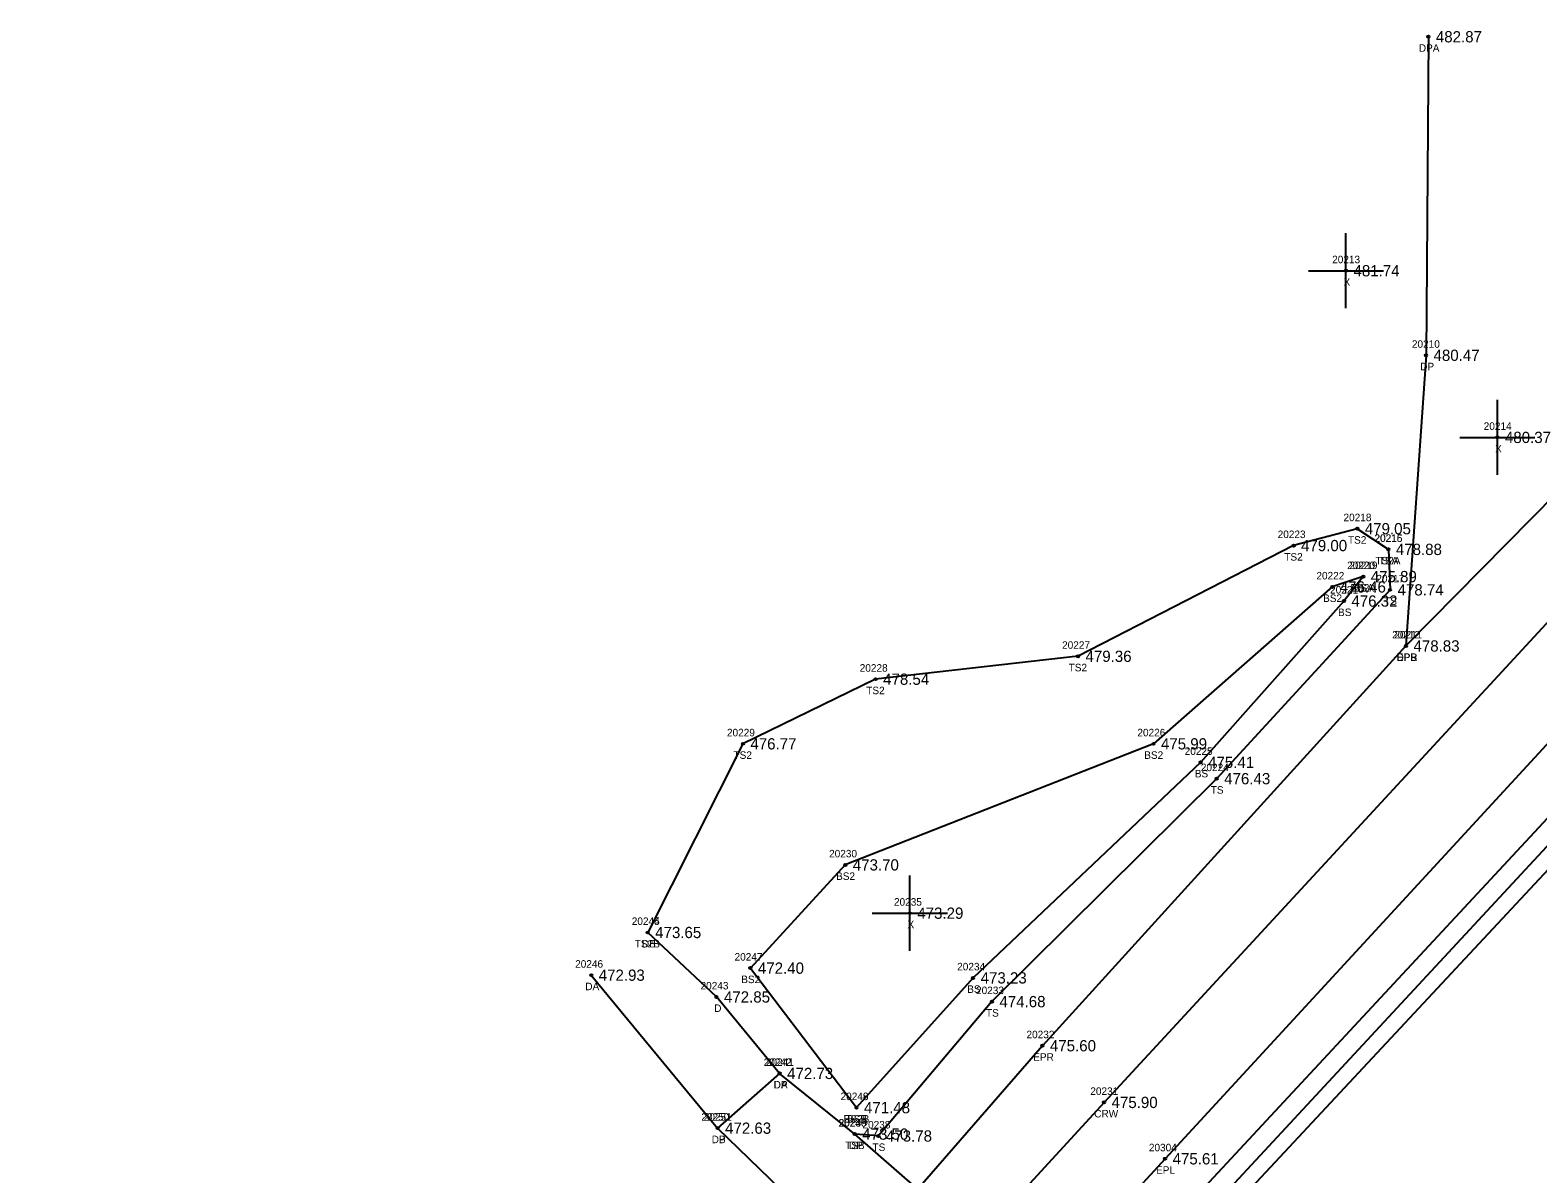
# Model space of a CAD drawing. Extents: x 1741010 to 1742139, y 749382 to 750625.
# Drawn here: x 1741600.6 to 1741801.4, y 750217 to 750369.4 of the extents above; entities that cross this region are included whole.
import ezdxf

# ---------------------------------------------------------------- set-up
doc = ezdxf.new("R2010")
doc.units = 0
for name, color, linetype in [('RD_DTM_BkLn1', 7, 'Continuous'), ('RD_DTM_BkLn2', 7, 'Continuous'), ('RD_DTM_BkLn_txCode', 7, 'Continuous'), ('RD_EX_Driveway', 7, 'Continuous'), ('RD_EX_Driveway_txCode', 7, 'Continuous'), ('RD_EX_Misc', 7, 'Continuous'), ('RD_EX_Misc_txCode', 7, 'Continuous'), ('RD_EX_Road', 7, 'Continuous'), ('RD_EX_Road_txCode', 7, 'Continuous'), ('RD_EX_TX_Driveway_ELEV', 7, 'Continuous'), ('RD_EX_TX_Misc_ELEV', 7, 'Continuous'), ('RD_EX_TX_Road_ELEV', 7, 'Continuous'), ('RD_HC_Survey_ELEV', 7, 'Continuous'), ('RD_HC_Survey_txCode', 7, 'Continuous'), ('RD_SMD_Locator', 7, 'Continuous')]:
    doc.layers.add(name, color=color, linetype=linetype)

msp = doc.modelspace()

# ---------------------------------------------------------------- linework, layer by layer
at = {"layer": 'RD_DTM_BkLn1'}
msp.add_lwpolyline([(1742095.1, 750579.47), (1742056.96, 750547.11), (1742019.74, 750514.22), (1741983.45, 750480.17), (1741948.01, 750445.01), (1741913.15, 750409.3), (1741879.03, 750372.99), (1741811.59, 750300.09), (1741743.65, 750226.52), (1741676.29, 750153.06), (1741642.32, 750115.53), (1741610.32, 750077.63)], dxfattribs=at)
at = {"layer": 'RD_DTM_BkLn2'}
for points in [[(1742105.6, 750567.48), (1742094.25, 750560.49), (1742091.64, 750555.7), (1742067.93, 750534.94), (1742031.73, 750501.95), (1741994.85, 750467.63), (1741959.82, 750432.06), (1741925.8, 750396.31), (1741891.25, 750362.62), (1741824.36, 750287.7), (1741756.44, 750214.6), (1741688.69, 750142.04), (1741655.55, 750103.43), (1741644.64, 750083.31), (1741626.06, 750060.3), (1741620, 750055.3), (1741614.97, 750059.12), (1741617.5, 750064.27), (1741619.23, 750067.96)], [(1742107.37, 750564.98), (1742099.21, 750558.66), (1742095.99, 750559.5), (1742095.15, 750554.39), (1742069.73, 750532.61), (1742034.06, 750499.81), (1741997.6, 750464.99), (1741961.88, 750429.54), (1741928.13, 750394.17), (1741895.34, 750359.02), (1741826.5, 750286.36), (1741758.73, 750213.29), (1741690.1, 750140.59), (1741658.36, 750099.77), (1741650.43, 750077.87), (1741632.9, 750061.59), (1741621.97, 750051.56), (1741618.99, 750048.78), (1741611.88, 750047.79)], [(1742108.6, 750563.87), (1742101.48, 750556.48), (1742102.57, 750548.5), (1742101.05, 750532.99), (1742105.06, 750513.92), (1742103.27, 750510.53), (1742100.54, 750509.6), (1742099.13, 750514.58), (1742095.78, 750530.6), (1742094.19, 750550.08), (1742071, 750531.59), (1742035.26, 750498.87), (1741998.91, 750463.73), (1741964.71, 750427.12), (1741930.26, 750392.09), (1741896.36, 750357.96), (1741828.15, 750284.74), (1741760.22, 750211.9), (1741691.37, 750138.81), (1741661.95, 750096.11), (1741655.14, 750072.69), (1741637.21, 750056.01), (1741627.61, 750046.43), (1741623.09, 750045.5)], [(1741781.51, 750300.19), (1741777.38, 750302.95), (1741768.89, 750300.7), (1741740.18, 750285.95), (1741713.23, 750282.9), (1741695.55, 750274.29), (1741682.87, 750249.16)], [(1741781.51, 750300.19), (1741781.74, 750294.8), (1741758.65, 750269.65), (1741728.72, 750239.95), (1741713.6, 750222.05), (1741710.44, 750222.3)], [(1741778.17, 750296.57), (1741774.05, 750295.19), (1741750.23, 750274.29), (1741709.19, 750258.16), (1741696.55, 750244.41), (1741710.68, 750225.83)], [(1741778.17, 750296.57), (1741775.59, 750293.31), (1741756.5, 750271.82), (1741726.21, 750243.11), (1741710.68, 750225.83)]]:
    msp.add_lwpolyline(points, dxfattribs=at)
at = {"layer": 'RD_EX_Driveway'}
msp.add_line((1741675.35, 750243.47), (1741692.18, 750223.09), dxfattribs=at)
for points in [[(1741786.84, 750368.48), (1741786.53, 750326.05), (1741783.86, 750287.33)], [(1741700.44, 750230.38), (1741692.03, 750240.57), (1741682.87, 750249.16)], [(1741718.84, 750214.98), (1741710.44, 750222.3), (1741700.44, 750230.38), (1741692.18, 750223.09), (1741710.25, 750205.58)]]:
    msp.add_lwpolyline(points, dxfattribs=at)
at = {"layer": 'RD_EX_Misc'}
for p, q in [((1741775.87, 750332.31), (1741775.87, 750342.31)), ((1741770.87, 750337.31), (1741780.87, 750337.31)), ((1741796.04, 750310.11), (1741796.04, 750320.11)), ((1741791.04, 750315.11), (1741801.04, 750315.11)), ((1741717.78, 750246.73), (1741717.78, 750256.73)), ((1741712.78, 750251.73), (1741722.78, 750251.73))]:
    msp.add_line(p, q, dxfattribs=at)
at = {"layer": 'RD_EX_Road'}
for points in [[(1742095.24, 750593.27), (1742088.27, 750587.97), (1742078.23, 750580.89), (1742049.13, 750555.21), (1742012.94, 750522.73), (1741975.54, 750488.03), (1741940.71, 750452.82), (1741916.22, 750428.67), (1741904.72, 750416.99), (1741884.38, 750395.02), (1741870.75, 750380.27), (1741817.36, 750322.98), (1741803.89, 750307.66), (1741783.86, 750287.33), (1741735.44, 750234.07), (1741718.84, 750214.98), (1741710.25, 750205.58), (1741668.97, 750159.8), (1741635, 750122.49), (1741604.35, 750087.7), (1741600.63, 750085.47)], [(1742102.43, 750570.61), (1742093.26, 750562.71), (1742064.72, 750538.42), (1742027.92, 750505.65), (1741991.25, 750471.83), (1741956.32, 750436.98), (1741921.43, 750401.39), (1741886.79, 750364.93), (1741819.64, 750292.67), (1741751.78, 750219.01), (1741684.42, 750145.59), (1741650.98, 750108.5), (1741637.17, 750092.42), (1741621.17, 750073.94), (1741621.31, 750072.22), (1741619.24, 750070.27)]]:
    msp.add_lwpolyline(points, dxfattribs=at)
at = {"layer": 'RD_SMD_Locator'}
for centre in [(1741786.84, 750368.48), (1741775.87, 750337.31), (1741786.53, 750326.05), (1741796.04, 750315.11), (1741777.38, 750302.95), (1741768.89, 750300.7), (1741781.51, 750300.19), (1741781.51, 750300.19), (1741774.05, 750295.19), (1741778.17, 750296.57), (1741778.17, 750296.57), (1741775.59, 750293.31), (1741781.74, 750294.8), (1741783.86, 750287.33), (1741783.86, 750287.33), (1741740.18, 750285.95), (1741713.23, 750282.9), (1741695.55, 750274.29), (1741750.23, 750274.29), (1741756.5, 750271.82), (1741758.65, 750269.65), (1741709.19, 750258.16), (1741717.78, 750251.73), (1741682.87, 750249.16), (1741682.87, 750249.16), (1741675.35, 750243.47), (1741696.55, 750244.41), (1741726.21, 750243.11), (1741692.03, 750240.57), (1741728.72, 750239.95), (1741735.44, 750234.07), (1741700.44, 750230.38), (1741700.44, 750230.38), (1741710.68, 750225.83), (1741710.68, 750225.83), (1741743.65, 750226.52), (1741692.18, 750223.09), (1741692.18, 750223.09), (1741710.44, 750222.3), (1741710.44, 750222.3), (1741713.6, 750222.05), (1741751.78, 750219.01)]:
    msp.add_circle(centre, 0.15, dxfattribs=at)

# ---------------------------------------------------------------- texts
at = {"layer": 'RD_DTM_BkLn_txCode'}
for s, p in [('20218', (1741775.54, 750303.95)), ('20223', (1741766.77, 750301.7)), ('TS2', (1741776.13, 750300.95)), ('20216', (1741779.65, 750301.19)), ('20215', (1741779.68, 750301.19)), ('TS2', (1741767.65, 750298.7)), ('20220', (1741776.02, 750297.57)), ('20219', (1741776.34, 750297.57)), ('TS2A', (1741779.78, 750298.19)), ('TSA', (1741780.23, 750298.19)), ('20222', (1741771.93, 750296.19)), ('20221', (1741773.75, 750294.31)), ('BS2A', (1741776.46, 750294.57)), ('BSA', (1741776.91, 750294.57)), ('20217', (1741779.91, 750295.8)), ('BS2', (1741772.82, 750293.19)), ('TS', (1741780.95, 750292.8)), ('BS', (1741774.81, 750291.31)), ('20227', (1741738.06, 750286.95)), ('20228', (1741711.11, 750283.9)), ('TS2', (1741738.93, 750283.95)), ('TS2', (1741711.98, 750280.9)), ('20229', (1741693.43, 750275.29)), ('20226', (1741748.09, 750275.29)), ('TS2', (1741694.3, 750272.29)), ('BS2', (1741749, 750272.29)), ('20225', (1741754.39, 750272.82)), ('20224', (1741756.54, 750270.65)), ('BS', (1741755.73, 750269.82)), ('TS', (1741757.86, 750267.65)), ('20230', (1741707.03, 750259.16)), ('BS2', (1741707.96, 750256.16)), ('20245', (1741680.75, 750250.16)), ('TS2B', (1741681.15, 750247.16)), ('20247', (1741694.44, 750245.41)), ('20234', (1741724.09, 750244.11)), ('BS2', (1741695.33, 750242.41)), ('BS', (1741725.43, 750241.11)), ('20233', (1741726.6, 750240.95)), ('TS', (1741727.92, 750237.95)), ('20248', (1741708.56, 750226.83)), ('20249', (1741708.56, 750226.83)), ('20239', (1741708.32, 750223.3)), ('BS2B', (1741708.97, 750223.83)), ('BSB', (1741709.42, 750223.83)), ('20238', (1741711.48, 750223.05)), ('TSB', (1741709.17, 750220.3)), ('TS', (1741712.81, 750220.05))]:
    msp.add_text(s, height=1, dxfattribs=at).set_placement(p)
at = {"layer": 'RD_EX_Driveway_txCode'}
for s, p in [('DPA', (1741785.57, 750366.48)), ('20210', (1741784.65, 750327.05)), ('DP', (1741785.75, 750324.05)), ('20211', (1741782.31, 750288.33)), ('DPB', (1741782.6, 750285.33)), ('20244', (1741680.75, 750250.16)), ('DB', (1741682.09, 750247.16)), ('20246', (1741673.21, 750244.47)), ('DA', (1741674.56, 750241.47)), ('20243', (1741689.91, 750241.57)), ('D', (1741691.73, 750238.57)), ('20242', (1741698.32, 750231.38)), ('20241', (1741698.6, 750231.38)), ('DA', (1741699.64, 750228.38)), ('DP', (1741699.66, 750228.38)), ('20250', (1741690.02, 750224.09)), ('20251', (1741690.34, 750224.09)), ('20240', (1741708.28, 750223.3)), ('DB', (1741691.4, 750221.09)), ('DP', (1741691.4, 750221.09)), ('DP', (1741709.66, 750220.3))]:
    msp.add_text(s, height=1, dxfattribs=at).set_placement(p)
at = {"layer": 'RD_EX_Misc_txCode'}
for s, p in [('20213', (1741774.03, 750338.31)), ('X', (1741775.55, 750335.31)), ('20214', (1741794.21, 750316.11)), ('X', (1741795.73, 750313.11)), ('20235', (1741715.67, 750252.73)), ('X', (1741717.47, 750249.73))]:
    msp.add_text(s, height=1, dxfattribs=at).set_placement(p)
at = {"layer": 'RD_EX_Road_txCode'}
for s, p in [('20212', (1741782.02, 750288.33)), ('EPR', (1741782.63, 750285.33)), ('20232', (1741733.32, 750235.07)), ('EPR', (1741734.21, 750232.07)), ('20304', (1741749.62, 750220.01)), ('EPL', (1741750.57, 750217.01))]:
    msp.add_text(s, height=1, dxfattribs=at).set_placement(p)
at = {"layer": 'RD_EX_TX_Driveway_ELEV'}
for s, p in [('482.87', (1741787.84, 750367.73)), ('480.47', (1741787.53, 750325.3)), ('478.83', (1741784.86, 750286.58)), ('473.65', (1741683.87, 750248.41)), ('472.93', (1741676.35, 750242.72)), ('472.85', (1741693.03, 750239.82)), ('472.73', (1741701.44, 750229.63)), ('472.73', (1741701.44, 750229.63)), ('472.63', (1741693.18, 750222.34)), ('472.63', (1741693.18, 750222.34)), ('473.50', (1741711.44, 750221.55))]:
    msp.add_text(s, height=1.5, dxfattribs=at).set_placement(p)
at = {"layer": 'RD_EX_TX_Misc_ELEV'}
for s, p in [('481.74', (1741776.87, 750336.56)), ('480.37', (1741797.04, 750314.36)), ('479.05', (1741778.38, 750302.2)), ('479.00', (1741769.89, 750299.95)), ('478.88', (1741782.51, 750299.44)), ('478.88', (1741782.51, 750299.44)), ('475.89', (1741779.17, 750295.82)), ('475.89', (1741779.17, 750295.82)), ('476.46', (1741775.05, 750294.44)), ('478.74', (1741782.74, 750294.05)), ('476.32', (1741776.59, 750292.56)), ('479.36', (1741741.18, 750285.2)), ('478.54', (1741714.23, 750282.15)), ('476.77', (1741696.55, 750273.54)), ('475.99', (1741751.23, 750273.54)), ('475.41', (1741757.5, 750271.07)), ('476.43', (1741759.65, 750268.9)), ('473.70', (1741710.19, 750257.41)), ('473.29', (1741718.78, 750250.98)), ('473.65', (1741683.87, 750248.41)), ('472.40', (1741697.55, 750243.66)), ('473.23', (1741727.21, 750242.36)), ('474.68', (1741729.72, 750239.2)), ('471.48', (1741711.68, 750225.08)), ('471.48', (1741711.68, 750225.08)), ('473.50', (1741711.44, 750221.55)), ('473.78', (1741714.6, 750221.3))]:
    msp.add_text(s, height=1.5, dxfattribs=at).set_placement(p)
at = {"layer": 'RD_EX_TX_Road_ELEV'}
for s, p in [('478.83', (1741784.86, 750286.58)), ('475.60', (1741736.44, 750233.32)), ('475.61', (1741752.78, 750218.26))]:
    msp.add_text(s, height=1.5, dxfattribs=at).set_placement(p)
at = {"layer": 'RD_HC_Survey_ELEV'}
msp.add_text('475.90', height=1.5, dxfattribs=at).set_placement((1741744.65, 750225.77))
at = {"layer": 'RD_HC_Survey_txCode'}
for s, p in [('20231', (1741741.82, 750227.52)), ('CRW', (1741742.34, 750224.52))]:
    msp.add_text(s, height=1, dxfattribs=at).set_placement(p)

doc.saveas('drawing.dxf')
